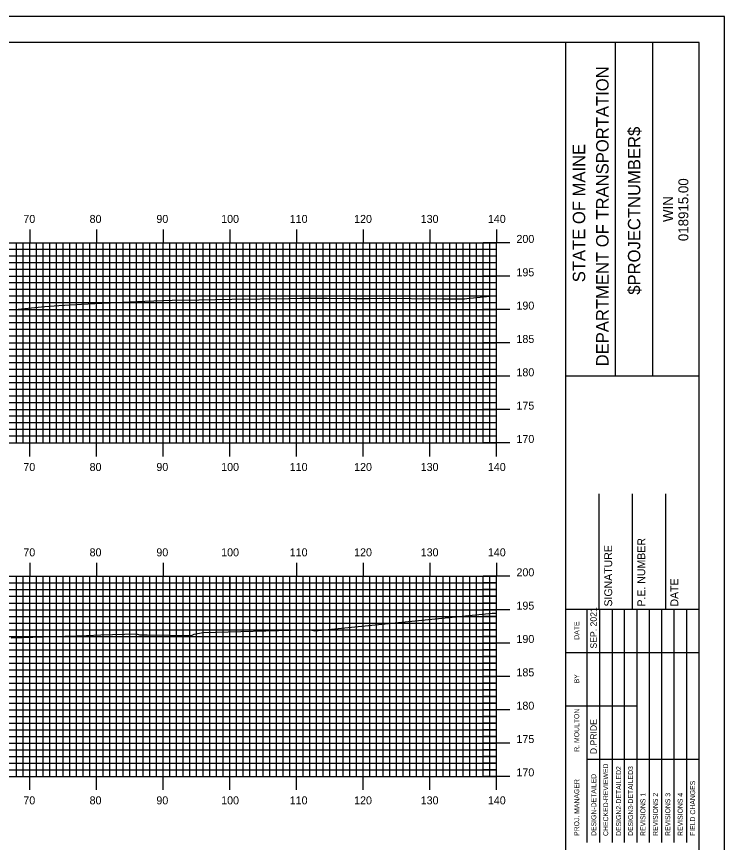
# Model space of a CAD drawing. Extents: x 1823966 to 1824309, y 442591 to 442811.
# Drawn here: x 1824199.8 to 1824306, y 442686.7 to 442810.5 of the extents above; entities that cross this region are included whole.
import ezdxf

# ---------------------------------------------------------------- set-up
doc = ezdxf.new("R2010")
doc.units = 0
for name, color, linetype in [('BORDER', 7, 'Continuous'), ('H_V ANNOTATION', 7, 'Continuous'), ('MAJOR', 7, 'Continuous'), ('MINOR', 7, 'Continuous'), ('PLOT BOUNDARY', 7, 'Continuous'), ('S_Roadway_Centerline', 7, 'Continuous')]:
    doc.layers.add(name, color=color, linetype=linetype)

msp = doc.modelspace()

# ---------------------------------------------------------------- linework, layer by layer
at = {"layer": 'BORDER'}
for p, q in [((1824282.22, 442596.67), (1824282.22, 442806.67)), ((1824289.68, 442756.66), (1824289.68, 442806.66)), ((1824295.27, 442756.66), (1824295.27, 442806.66)), ((1824282.22, 442756.65), (1824302.22, 442756.65)), ((1824287.22, 442721.67), (1824287.22, 442738.97)), ((1824292.22, 442721.67), (1824292.22, 442738.97)), ((1824297.22, 442721.67), (1824297.22, 442738.97)), ((1824282.22, 442721.67), (1824302.22, 442721.67))]:
    msp.add_line(p, q, dxfattribs=at)
msp.add_lwpolyline([(1823982.22, 442596.67), (1824302.22, 442596.67), (1824302.22, 442806.67), (1823982.22, 442806.67)], close=True, dxfattribs=at)
for points in [[(1824285.45, 442715.17), (1824285.45, 442721.67)], [(1824287.32, 442686.68), (1824287.32, 442721.67)], [(1824289.18, 442721.67), (1824289.18, 442686.68)], [(1824291.04, 442686.68), (1824291.04, 442721.67)], [(1824292.91, 442686.68), (1824292.91, 442721.67)], [(1824294.77, 442686.68), (1824294.77, 442721.67)], [(1824296.63, 442686.68), (1824296.63, 442721.67)], [(1824298.5, 442686.68), (1824298.5, 442721.67)], [(1824300.36, 442686.68), (1824300.36, 442721.67)], [(1824285.45, 442686.68), (1824285.45, 442720.26)], [(1824282.22, 442715.17), (1824302.22, 442715.17)], [(1824282.22, 442707.17), (1824285.45, 442707.17)], [(1824285.45, 442707.17), (1824292.9, 442707.17)], [(1824285.45, 442699.17), (1824302.22, 442699.17)]]:
    msp.add_lwpolyline(points, dxfattribs=at)
at = {"layer": 'MAJOR'}
for p, q in [((1824201.82, 442778.59), (1824201.82, 442776.59)), ((1824211.82, 442778.59), (1824211.82, 442776.59)), ((1824221.82, 442778.59), (1824221.82, 442776.59)), ((1824231.82, 442778.59), (1824231.82, 442776.59)), ((1824241.82, 442778.59), (1824241.82, 442776.59)), ((1824251.82, 442778.59), (1824251.82, 442776.59)), ((1824261.82, 442778.59), (1824261.82, 442776.59)), ((1824271.82, 442778.59), (1824271.82, 442776.59)), ((1823991.82, 442776.59), (1824271.82, 442776.59)), ((1824201.82, 442746.59), (1824201.82, 442776.59)), ((1824211.82, 442746.59), (1824211.82, 442776.59)), ((1824221.82, 442746.59), (1824221.82, 442776.59)), ((1824231.82, 442746.59), (1824231.82, 442776.59)), ((1824241.82, 442746.59), (1824241.82, 442776.59)), ((1824251.82, 442746.59), (1824251.82, 442776.59)), ((1824261.82, 442746.59), (1824261.82, 442776.59)), ((1824273.83, 442776.59), (1824269.82, 442776.59)), ((1824271.82, 442746.59), (1824271.82, 442776.59)), ((1824271.82, 442746.59), (1824271.82, 442776.59)), ((1823991.82, 442771.59), (1824271.82, 442771.59)), ((1824273.83, 442771.59), (1824269.82, 442771.59)), ((1823991.82, 442766.59), (1824271.82, 442766.59)), ((1824273.83, 442766.59), (1824269.82, 442766.59)), ((1823991.82, 442761.59), (1824271.82, 442761.59)), ((1824273.83, 442761.59), (1824269.82, 442761.59)), ((1823991.82, 442756.59), (1824271.82, 442756.59)), ((1824273.83, 442756.59), (1824269.82, 442756.59)), ((1823991.82, 442751.59), (1824271.82, 442751.59)), ((1824273.83, 442751.59), (1824269.82, 442751.59)), ((1823991.82, 442746.59), (1824271.82, 442746.59)), ((1823991.82, 442746.59), (1824271.82, 442746.59)), ((1824201.82, 442744.58), (1824201.82, 442746.59)), ((1824211.82, 442744.58), (1824211.82, 442746.59)), ((1824221.82, 442744.58), (1824221.82, 442746.59)), ((1824231.82, 442744.58), (1824231.82, 442746.59)), ((1824241.82, 442744.58), (1824241.82, 442746.59)), ((1824251.82, 442744.58), (1824251.82, 442746.59)), ((1824261.82, 442744.58), (1824261.82, 442746.59)), ((1824273.83, 442746.59), (1824269.82, 442746.59)), ((1824271.82, 442744.58), (1824271.82, 442746.59)), ((1824201.82, 442728.59), (1824201.82, 442726.59)), ((1824211.82, 442728.59), (1824211.82, 442726.59)), ((1824221.82, 442728.59), (1824221.82, 442726.59)), ((1824241.82, 442728.59), (1824241.82, 442726.59)), ((1824251.82, 442728.59), (1824251.82, 442726.59)), ((1824261.82, 442728.59), (1824261.82, 442726.59)), ((1824271.82, 442728.59), (1824271.82, 442726.59)), ((1823991.82, 442726.59), (1824271.82, 442726.59)), ((1823991.82, 442726.59), (1824271.82, 442726.59)), ((1824201.82, 442696.59), (1824201.82, 442726.59)), ((1824211.82, 442696.59), (1824211.82, 442726.59)), ((1824221.82, 442696.59), (1824221.82, 442726.59)), ((1824231.82, 442696.59), (1824231.82, 442726.59)), ((1824231.82, 442726.51), (1824231.82, 442724.51)), ((1824241.82, 442696.59), (1824241.82, 442726.59)), ((1824251.82, 442696.59), (1824251.82, 442726.59)), ((1824261.82, 442696.59), (1824261.82, 442726.59)), ((1824273.83, 442726.59), (1824269.82, 442726.59)), ((1824271.82, 442696.59), (1824271.82, 442726.59)), ((1824271.82, 442696.59), (1824271.82, 442726.59)), ((1823991.82, 442721.59), (1824271.82, 442721.59)), ((1824273.83, 442721.59), (1824269.82, 442721.59)), ((1823991.82, 442716.59), (1824271.82, 442716.59)), ((1824273.83, 442716.59), (1824269.82, 442716.59)), ((1823991.82, 442711.59), (1824271.82, 442711.59)), ((1824273.83, 442711.59), (1824269.82, 442711.59)), ((1823991.82, 442706.59), (1824271.82, 442706.59)), ((1824273.83, 442706.59), (1824269.82, 442706.59)), ((1823991.82, 442701.59), (1824271.82, 442701.59)), ((1824273.83, 442701.59), (1824269.82, 442701.59)), ((1823991.82, 442696.59), (1824271.82, 442696.59)), ((1823991.82, 442696.59), (1824271.82, 442696.59)), ((1824201.82, 442694.58), (1824201.82, 442696.59)), ((1824211.82, 442694.58), (1824211.82, 442696.59)), ((1824221.82, 442694.58), (1824221.82, 442696.59)), ((1824231.82, 442694.58), (1824231.82, 442696.59)), ((1824241.82, 442694.58), (1824241.82, 442696.59)), ((1824251.82, 442694.58), (1824251.82, 442696.59)), ((1824261.82, 442694.58), (1824261.82, 442696.59)), ((1824273.83, 442696.59), (1824269.82, 442696.59)), ((1824271.82, 442694.58), (1824271.82, 442696.59))]:
    msp.add_line(p, q, dxfattribs=at)
at = {"layer": 'MINOR'}
for p, q in [((1824199.82, 442746.59), (1824199.82, 442776.59)), ((1824200.82, 442746.59), (1824200.82, 442776.59)), ((1824202.82, 442746.59), (1824202.82, 442776.59)), ((1824203.82, 442746.59), (1824203.82, 442776.59)), ((1824204.82, 442746.59), (1824204.82, 442776.59)), ((1824205.82, 442746.59), (1824205.82, 442776.59)), ((1824206.82, 442746.59), (1824206.82, 442776.59)), ((1824207.82, 442746.59), (1824207.82, 442776.59)), ((1824208.82, 442746.59), (1824208.82, 442776.59)), ((1824209.82, 442746.59), (1824209.82, 442776.59)), ((1824210.82, 442746.59), (1824210.82, 442776.59)), ((1824212.82, 442746.59), (1824212.82, 442776.59)), ((1824213.82, 442746.59), (1824213.82, 442776.59)), ((1824214.82, 442746.59), (1824214.82, 442776.59)), ((1824215.82, 442746.59), (1824215.82, 442776.59)), ((1824216.82, 442746.59), (1824216.82, 442776.59)), ((1824217.82, 442746.59), (1824217.82, 442776.59)), ((1824218.82, 442746.59), (1824218.82, 442776.59)), ((1824219.82, 442746.59), (1824219.82, 442776.59)), ((1824220.82, 442746.59), (1824220.82, 442776.59)), ((1824222.82, 442746.59), (1824222.82, 442776.59)), ((1824223.82, 442746.59), (1824223.82, 442776.59)), ((1824224.82, 442746.59), (1824224.82, 442776.59)), ((1824225.82, 442746.59), (1824225.82, 442776.59)), ((1824226.82, 442746.59), (1824226.82, 442776.59)), ((1824227.82, 442746.59), (1824227.82, 442776.59)), ((1824228.82, 442746.59), (1824228.82, 442776.59)), ((1824229.82, 442746.59), (1824229.82, 442776.59)), ((1824230.82, 442746.59), (1824230.82, 442776.59)), ((1824232.82, 442746.59), (1824232.82, 442776.59)), ((1824233.82, 442746.59), (1824233.82, 442776.59)), ((1824234.82, 442746.59), (1824234.82, 442776.59)), ((1824235.82, 442746.59), (1824235.82, 442776.59)), ((1824236.82, 442746.59), (1824236.82, 442776.59)), ((1824237.82, 442746.59), (1824237.82, 442776.59)), ((1824238.82, 442746.59), (1824238.82, 442776.59)), ((1824239.82, 442746.59), (1824239.82, 442776.59)), ((1824240.82, 442746.59), (1824240.82, 442776.59)), ((1824242.82, 442746.59), (1824242.82, 442776.59)), ((1824243.82, 442746.59), (1824243.82, 442776.59)), ((1824244.82, 442746.59), (1824244.82, 442776.59)), ((1824245.82, 442746.59), (1824245.82, 442776.59)), ((1824246.82, 442746.59), (1824246.82, 442776.59)), ((1824247.82, 442746.59), (1824247.82, 442776.59)), ((1824248.82, 442746.59), (1824248.82, 442776.59)), ((1824249.82, 442746.59), (1824249.82, 442776.59)), ((1824250.82, 442746.59), (1824250.82, 442776.59)), ((1824252.82, 442746.59), (1824252.82, 442776.59)), ((1824253.82, 442746.59), (1824253.82, 442776.59)), ((1824254.82, 442746.59), (1824254.82, 442776.59)), ((1824255.82, 442746.59), (1824255.82, 442776.59)), ((1824256.82, 442746.59), (1824256.82, 442776.59)), ((1824257.82, 442746.59), (1824257.82, 442776.59)), ((1824258.82, 442746.59), (1824258.82, 442776.59)), ((1824259.82, 442746.59), (1824259.82, 442776.59)), ((1824260.82, 442746.59), (1824260.82, 442776.59)), ((1824262.82, 442746.59), (1824262.82, 442776.59)), ((1824263.82, 442746.59), (1824263.82, 442776.59)), ((1824264.82, 442746.59), (1824264.82, 442776.59)), ((1824265.82, 442746.59), (1824265.82, 442776.59)), ((1824266.82, 442746.59), (1824266.82, 442776.59)), ((1824267.82, 442746.59), (1824267.82, 442776.59)), ((1824268.82, 442746.59), (1824268.82, 442776.59)), ((1824269.82, 442746.59), (1824269.82, 442776.59)), ((1824270.82, 442746.59), (1824270.82, 442776.59)), ((1823991.82, 442775.67), (1824271.82, 442775.67)), ((1824271.82, 442775.59), (1824269.82, 442775.59)), ((1823991.82, 442774.67), (1824271.82, 442774.67)), ((1823991.82, 442773.67), (1824271.82, 442773.67)), ((1824271.82, 442774.59), (1824269.82, 442774.59)), ((1824271.82, 442773.59), (1824269.82, 442773.59)), ((1823991.82, 442772.67), (1824271.82, 442772.67)), ((1824271.82, 442772.59), (1824269.82, 442772.59)), ((1823991.82, 442770.67), (1824271.82, 442770.67)), ((1824271.82, 442770.59), (1824269.82, 442770.59)), ((1823991.82, 442769.67), (1824271.82, 442769.67)), ((1823991.82, 442768.67), (1824271.82, 442768.67)), ((1824271.82, 442769.59), (1824269.82, 442769.59)), ((1824271.82, 442768.59), (1824269.82, 442768.59)), ((1823991.82, 442767.67), (1824271.82, 442767.67)), ((1824271.82, 442767.59), (1824269.82, 442767.59)), ((1823991.82, 442765.67), (1824271.82, 442765.67)), ((1824271.82, 442765.59), (1824269.82, 442765.59)), ((1823991.82, 442764.67), (1824271.82, 442764.67)), ((1823991.82, 442763.67), (1824271.82, 442763.67)), ((1824271.82, 442764.59), (1824269.82, 442764.59)), ((1824271.82, 442763.59), (1824269.82, 442763.59)), ((1823991.82, 442762.67), (1824271.82, 442762.67)), ((1824271.82, 442762.59), (1824269.82, 442762.59)), ((1823991.82, 442760.67), (1824271.82, 442760.67)), ((1824271.82, 442760.59), (1824269.82, 442760.59)), ((1823991.82, 442759.67), (1824271.82, 442759.67)), ((1823991.82, 442758.67), (1824271.82, 442758.67)), ((1824271.82, 442759.59), (1824269.82, 442759.59)), ((1823991.82, 442757.67), (1824271.82, 442757.67)), ((1824271.82, 442758.59), (1824269.82, 442758.59)), ((1824271.82, 442757.59), (1824269.82, 442757.59)), ((1823991.82, 442755.67), (1824271.82, 442755.67)), ((1824271.82, 442755.59), (1824269.82, 442755.59)), ((1823991.82, 442754.67), (1824271.82, 442754.67)), ((1823991.82, 442753.67), (1824271.82, 442753.67)), ((1824271.82, 442754.59), (1824269.82, 442754.59)), ((1823991.82, 442752.67), (1824271.82, 442752.67)), ((1824271.82, 442753.59), (1824269.82, 442753.59)), ((1824271.82, 442752.59), (1824269.82, 442752.59)), ((1823991.82, 442750.67), (1824271.82, 442750.67)), ((1824271.82, 442750.59), (1824269.82, 442750.59)), ((1823991.82, 442749.67), (1824271.82, 442749.67)), ((1824271.82, 442749.59), (1824269.82, 442749.59)), ((1823991.82, 442748.67), (1824271.82, 442748.67)), ((1823991.82, 442747.67), (1824271.82, 442747.67)), ((1824271.82, 442748.59), (1824269.82, 442748.59)), ((1824271.82, 442747.59), (1824269.82, 442747.59)), ((1824199.82, 442696.59), (1824199.82, 442726.59)), ((1824200.82, 442696.59), (1824200.82, 442726.59)), ((1824202.82, 442696.59), (1824202.82, 442726.59)), ((1824203.82, 442696.59), (1824203.82, 442726.59)), ((1824204.82, 442696.59), (1824204.82, 442726.59)), ((1824205.82, 442696.59), (1824205.82, 442726.59)), ((1824206.82, 442696.59), (1824206.82, 442726.59)), ((1824207.82, 442696.59), (1824207.82, 442726.59)), ((1824208.82, 442696.59), (1824208.82, 442726.59)), ((1824209.82, 442696.59), (1824209.82, 442726.59)), ((1824210.82, 442696.59), (1824210.82, 442726.59)), ((1824212.82, 442696.59), (1824212.82, 442726.59)), ((1824213.82, 442696.59), (1824213.82, 442726.59)), ((1824214.82, 442696.59), (1824214.82, 442726.59)), ((1824215.82, 442696.59), (1824215.82, 442726.59)), ((1824216.82, 442696.59), (1824216.82, 442726.59)), ((1824217.82, 442696.59), (1824217.82, 442726.59)), ((1824218.82, 442696.59), (1824218.82, 442726.59)), ((1824219.82, 442696.59), (1824219.82, 442726.59)), ((1824220.82, 442696.59), (1824220.82, 442726.59)), ((1824222.82, 442696.59), (1824222.82, 442726.59)), ((1824223.82, 442696.59), (1824223.82, 442726.59)), ((1824224.82, 442696.59), (1824224.82, 442726.59)), ((1824225.82, 442696.59), (1824225.82, 442726.59)), ((1824226.82, 442696.59), (1824226.82, 442726.59)), ((1824227.82, 442696.59), (1824227.82, 442726.59)), ((1824228.82, 442696.59), (1824228.82, 442726.59)), ((1824229.82, 442696.59), (1824229.82, 442726.59)), ((1824230.82, 442696.59), (1824230.82, 442726.59)), ((1824232.82, 442696.59), (1824232.82, 442726.59)), ((1824233.82, 442696.59), (1824233.82, 442726.59)), ((1824234.82, 442696.59), (1824234.82, 442726.59)), ((1824235.82, 442696.59), (1824235.82, 442726.59)), ((1824236.82, 442696.59), (1824236.82, 442726.59)), ((1824237.82, 442696.59), (1824237.82, 442726.59)), ((1824238.82, 442696.59), (1824238.82, 442726.59)), ((1824239.82, 442696.59), (1824239.82, 442726.59)), ((1824240.82, 442696.59), (1824240.82, 442726.59)), ((1824242.82, 442696.59), (1824242.82, 442726.59)), ((1824243.82, 442696.59), (1824243.82, 442726.59)), ((1824244.82, 442696.59), (1824244.82, 442726.59)), ((1824245.82, 442696.59), (1824245.82, 442726.59)), ((1824246.82, 442696.59), (1824246.82, 442726.59)), ((1824247.82, 442696.59), (1824247.82, 442726.59)), ((1824248.82, 442696.59), (1824248.82, 442726.59)), ((1824249.82, 442696.59), (1824249.82, 442726.59)), ((1824250.82, 442696.59), (1824250.82, 442726.59)), ((1824252.82, 442696.59), (1824252.82, 442726.59)), ((1824253.82, 442696.59), (1824253.82, 442726.59)), ((1824254.82, 442696.59), (1824254.82, 442726.59)), ((1824255.82, 442696.59), (1824255.82, 442726.59)), ((1824256.82, 442696.59), (1824256.82, 442726.59)), ((1824257.82, 442696.59), (1824257.82, 442726.59)), ((1824258.82, 442696.59), (1824258.82, 442726.59)), ((1824259.82, 442696.59), (1824259.82, 442726.59)), ((1824260.82, 442696.59), (1824260.82, 442726.59)), ((1824262.82, 442696.59), (1824262.82, 442726.59)), ((1824263.82, 442696.59), (1824263.82, 442726.59)), ((1824264.82, 442696.59), (1824264.82, 442726.59)), ((1824265.82, 442696.59), (1824265.82, 442726.59)), ((1824266.82, 442696.59), (1824266.82, 442726.59)), ((1824267.82, 442696.59), (1824267.82, 442726.59)), ((1824268.82, 442696.59), (1824268.82, 442726.59)), ((1824269.82, 442696.59), (1824269.82, 442726.59)), ((1824270.82, 442696.59), (1824270.82, 442726.59)), ((1823991.82, 442725.59), (1824271.82, 442725.59)), ((1824271.82, 442725.59), (1824269.82, 442725.59)), ((1823991.82, 442724.59), (1824271.82, 442724.59)), ((1824271.82, 442724.59), (1824269.82, 442724.59)), ((1823991.82, 442723.59), (1824271.82, 442723.59)), ((1824271.82, 442723.59), (1824269.82, 442723.59)), ((1823991.82, 442722.59), (1824271.82, 442722.59)), ((1824271.82, 442722.59), (1824269.82, 442722.59)), ((1823991.82, 442720.59), (1824271.82, 442720.59)), ((1824271.82, 442720.59), (1824269.82, 442720.59)), ((1823991.82, 442719.59), (1824271.82, 442719.59)), ((1824271.82, 442719.59), (1824269.82, 442719.59)), ((1823991.82, 442718.59), (1824271.82, 442718.59)), ((1824271.82, 442718.59), (1824269.82, 442718.59)), ((1823991.82, 442717.59), (1824271.82, 442717.59)), ((1824271.82, 442717.59), (1824269.82, 442717.59)), ((1823991.82, 442715.59), (1824271.82, 442715.59)), ((1824271.82, 442715.59), (1824269.82, 442715.59)), ((1823991.82, 442714.59), (1824271.82, 442714.59)), ((1824271.82, 442714.59), (1824269.82, 442714.59)), ((1823991.82, 442713.59), (1824271.82, 442713.59)), ((1824271.82, 442713.59), (1824269.82, 442713.59)), ((1823991.82, 442712.59), (1824271.82, 442712.59)), ((1824271.82, 442712.59), (1824269.82, 442712.59)), ((1823991.82, 442710.59), (1824271.82, 442710.59)), ((1824271.82, 442710.59), (1824269.82, 442710.59)), ((1823991.82, 442709.59), (1824271.82, 442709.59)), ((1824271.82, 442709.59), (1824269.82, 442709.59)), ((1823991.82, 442708.59), (1824271.82, 442708.59)), ((1824271.82, 442708.59), (1824269.82, 442708.59)), ((1823991.82, 442707.59), (1824271.82, 442707.59)), ((1824271.82, 442707.59), (1824269.82, 442707.59)), ((1823991.82, 442705.59), (1824271.82, 442705.59)), ((1824271.82, 442705.59), (1824269.82, 442705.59)), ((1823991.82, 442704.59), (1824271.82, 442704.59)), ((1824271.82, 442704.59), (1824269.82, 442704.59)), ((1823991.82, 442703.59), (1824271.82, 442703.59)), ((1824271.82, 442703.59), (1824269.82, 442703.59)), ((1823991.82, 442702.59), (1824271.82, 442702.59)), ((1824271.82, 442702.59), (1824269.82, 442702.59)), ((1823991.82, 442700.59), (1824271.82, 442700.59)), ((1824271.82, 442700.59), (1824269.82, 442700.59)), ((1823991.82, 442699.59), (1824271.82, 442699.59)), ((1824271.82, 442699.59), (1824269.82, 442699.59)), ((1823991.82, 442698.59), (1824271.82, 442698.59)), ((1824271.82, 442698.59), (1824269.82, 442698.59)), ((1823991.82, 442697.59), (1824271.82, 442697.59)), ((1824271.82, 442697.59), (1824269.82, 442697.59))]:
    msp.add_line(p, q, dxfattribs=at)
at = {"layer": 'PLOT BOUNDARY'}
msp.add_lwpolyline([(1823966.04, 442590.55), (1824306.04, 442590.55), (1824306.04, 442810.55), (1823966.04, 442810.55)], close=True, dxfattribs=at)
at = {"layer": 'S_Roadway_Centerline'}
for points in [[(1824199.4, 442766.62), (1824200.05, 442766.67), (1824204.03, 442767.05), (1824206.17, 442767.22), (1824209.57, 442767.43), (1824213.6, 442767.6), (1824213.92, 442767.62), (1824214.28, 442767.64), (1824214.43, 442767.64), (1824214.62, 442767.65), (1824219.04, 442767.88), (1824223.14, 442768), (1824227.15, 442768.06), (1824232.12, 442768.14), (1824240.65, 442768.25), (1824242.44, 442768.29), (1824245.34, 442768.3), (1824246.41, 442768.3), (1824250.43, 442768.26), (1824251.88, 442768.26), (1824252.79, 442768.27), (1824254.31, 442768.29), (1824263.77, 442768.2), (1824264.42, 442768.21), (1824264.76, 442768.21), (1824265.33, 442768.19), (1824266.13, 442768.2), (1824267.02, 442768.22), (1824267.37, 442768.24), (1824271.82, 442768.72)], [(1824198.98, 442717.37), (1824210.29, 442717.72), (1824212.45, 442717.81), (1824217.76, 442717.98), (1824218.25, 442717.8), (1824219.39, 442717.84), (1824226.08, 442717.73), (1824226.46, 442717.93), (1824227.76, 442718.16), (1824242.9, 442718.55), (1824243.91, 442718.57), (1824244.58, 442718.4), (1824271.19, 442721.05), (1824271.59, 442721.07), (1824271.67, 442721.09), (1824271.82, 442721.07)]]:
    msp.add_lwpolyline(points, dxfattribs=at)

# ---------------------------------------------------------------- texts
at = {"layer": 'BORDER'}
for s, height, p in [('DEPARTMENT OF TRANSPORTATION', 1.8635, (1824288.64, 442758.08)), ('$PROJECTNUMBER$', 1.8635, (1824293.41, 442768.82)), ('STATE OF MAINE', 1.8635, (1824285.13, 442770.69)), ('018915.00', 1.491, (1824300.61, 442776.86)), ('WIN', 1.491, (1824298.3, 442779.73)), ('P.E. NUMBER', 1.1811, (1824294.14, 442722.06)), ('SIGNATURE', 1.181, (1824289.18, 442722.06)), ('DATE', 1.181, (1824299.1, 442722.06)), ('SEP. 2021', 0.969, (1824286.87, 442715.76)), ('DATE', 0.743, (1824284.23, 442717.08)), ('BY', 0.743, (1824284.23, 442710.54)), ('R. MOULTON', 0.745, (1824284.23, 442700.28)), ('D.PRIDE', 0.969, (1824286.87, 442699.92)), ('CHECKED-REVIEWED', 0.7455, (1824288.58, 442687.65)), ('DESIGN2-DETAILED2', 0.7455, (1824290.52, 442687.65)), ('DESIGN3-DETAILED3', 0.7455, (1824292.31, 442687.65)), ('PROJ. MANAGER', 0.7455, (1824284.23, 442687.65)), ('DESIGN-DETAILED', 0.7455, (1824286.79, 442687.65)), ('FIELD CHANGES', 0.7455, (1824301.63, 442687.65)), ('REVISIONS 1', 0.7455, (1824294.17, 442687.65)), ('REVISIONS 2', 0.7455, (1824296.04, 442687.65)), ('REVISIONS 3', 0.7455, (1824297.9, 442687.65)), ('REVISIONS 4', 0.7455, (1824299.76, 442687.65))]:
    msp.add_text(s, height=height, rotation=90, dxfattribs=at).set_placement(p)
at = {"layer": 'H_V ANNOTATION'}
for s, p in [('70', (1824200.83, 442779.59)), ('80', (1824210.77, 442779.59)), ('90', (1824220.79, 442779.59)), ('100', (1824230.51, 442779.59)), ('110', (1824240.8, 442779.59)), ('120', (1824250.46, 442779.59)), ('130', (1824260.45, 442779.59)), ('140', (1824270.53, 442779.59)), ('200', (1824274.82, 442776.59)), ('195', (1824274.82, 442771.59)), ('190', (1824274.82, 442766.59)), ('185', (1824274.82, 442761.59)), ('180', (1824274.82, 442756.59)), ('175', (1824274.82, 442751.59)), ('170', (1824274.82, 442746.59)), ('70', (1824200.83, 442742.39)), ('80', (1824210.77, 442742.39)), ('90', (1824220.79, 442742.39)), ('100', (1824230.51, 442742.39)), ('110', (1824240.8, 442742.39)), ('120', (1824250.46, 442742.39)), ('130', (1824260.45, 442742.39)), ('140', (1824270.53, 442742.39)), ('70', (1824200.83, 442729.59)), ('80', (1824210.77, 442729.59)), ('90', (1824220.79, 442729.59)), ('100', (1824230.51, 442729.59)), ('110', (1824240.8, 442729.59)), ('120', (1824250.46, 442729.59)), ('130', (1824260.45, 442729.59)), ('140', (1824270.53, 442729.59)), ('200', (1824274.82, 442726.59)), ('195', (1824274.82, 442721.59)), ('190', (1824274.82, 442716.59)), ('185', (1824274.82, 442711.59)), ('180', (1824274.82, 442706.59)), ('175', (1824274.82, 442701.59)), ('170', (1824274.82, 442696.59)), ('70', (1824200.83, 442692.39)), ('80', (1824210.77, 442692.39)), ('90', (1824220.79, 442692.39)), ('100', (1824230.51, 442692.39)), ('110', (1824240.8, 442692.39)), ('120', (1824250.46, 442692.39)), ('130', (1824260.45, 442692.39)), ('140', (1824270.53, 442692.39))]:
    msp.add_text(s, height=1.2, dxfattribs=at).set_placement(p)

doc.saveas('drawing.dxf')
